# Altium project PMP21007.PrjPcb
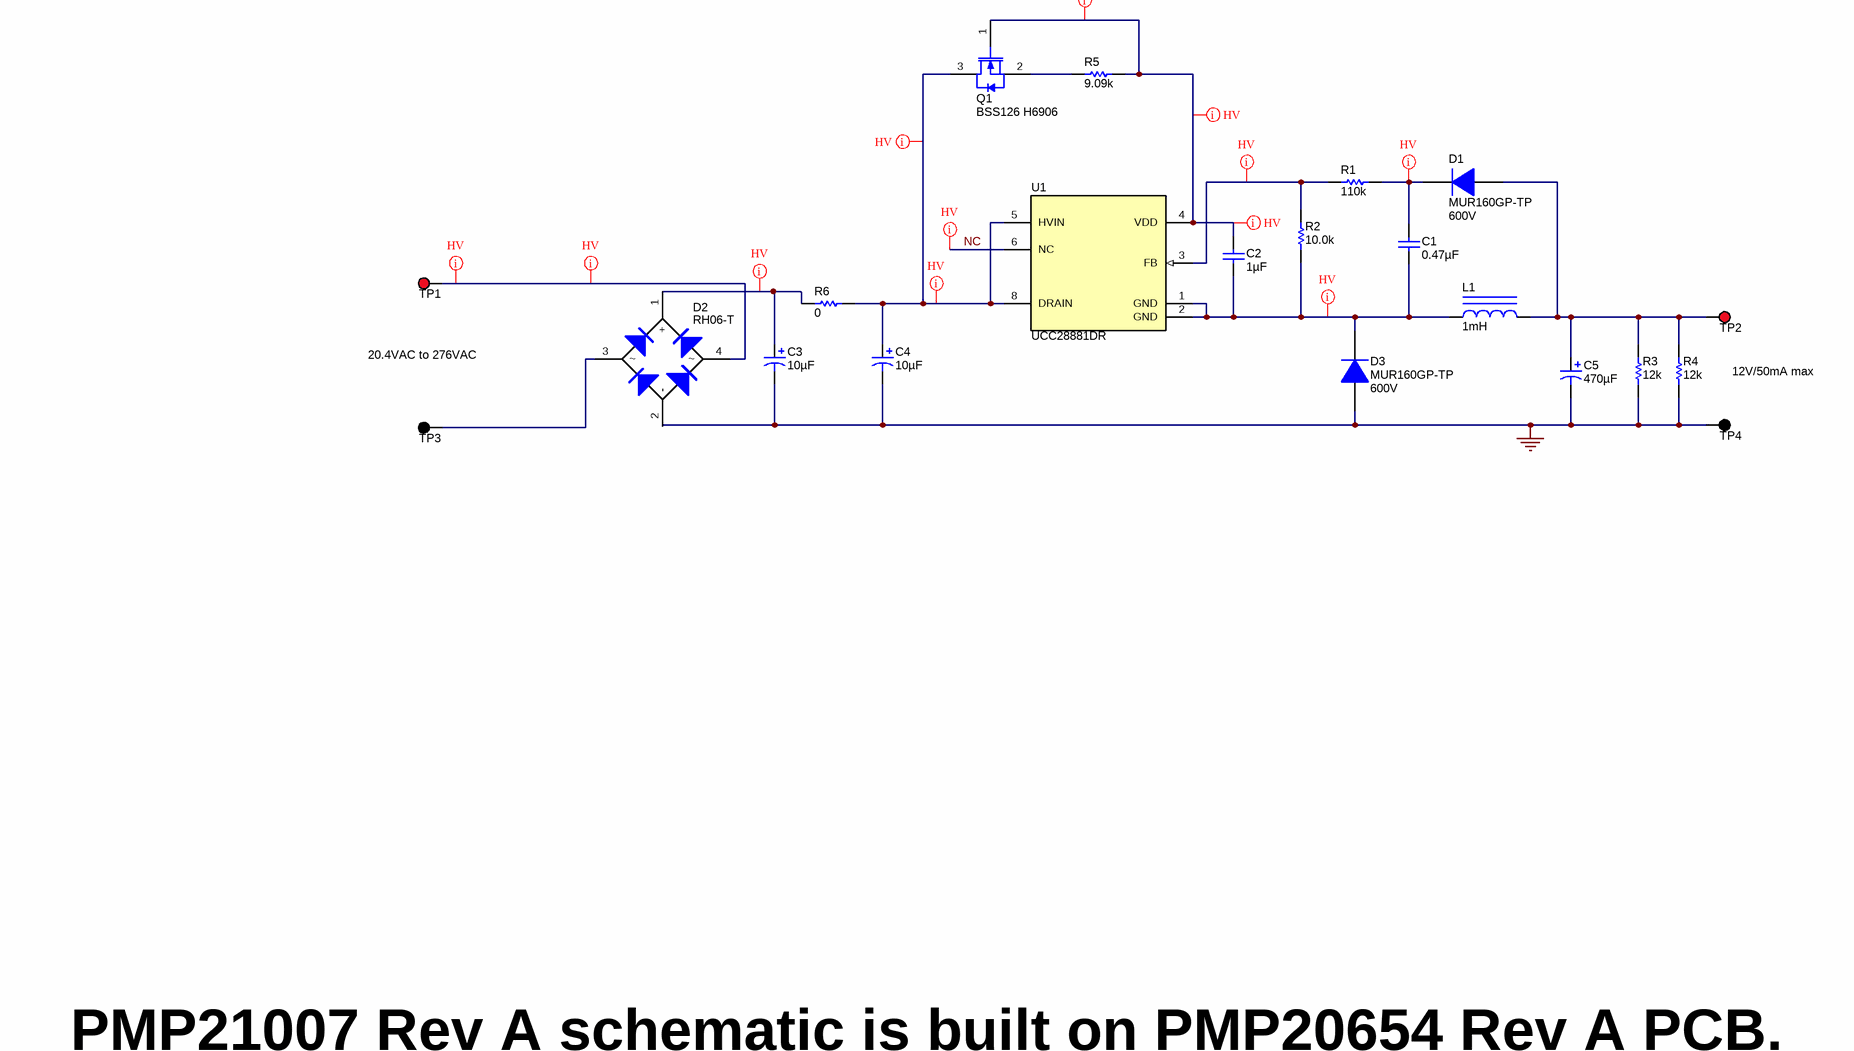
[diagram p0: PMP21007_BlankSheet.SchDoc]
CopyrightYear: 2017; PCB_Rev: A; PRJ_Customer: Public Release; PRJ_Engineer: Sonal Singh; PRJ_Number: PMP21007; PRJ_Title: UCC28881 High side Buck; SCH_Rev: A; TechSupport: http://www.ti.com/support; TID: N/A
1 sheet, 21 parts. Net scope: global (net labels, ports and power ports of the same name join across sheets).
Board file: PMP21007_PCB.PcbDoc

## Sheet PMP21007_BlankSheet.SchDoc
size 431 x 279 mm; Date: Not shown in title block; ApprovedBy: Not shown in title block; CheckedBy: Not shown in title block; Author: Not shown in title block; CompanyName: Not shown in title block; Engineer: Not shown in title block; Organization: Not shown in title block; Address1: Not shown in title block; Address2: Not shown in title block; Address3: Not shown in title block; Address4: Not shown in title block; DocumentNumber: 1; Revision: Use project parameter SCH_Rev; SheetNumber: 1; SheetTotal: 1; PageSetup: Record=PageOptions¦CenterHorizontal=True¦CenterVertical=True¦PrintScale=1.00¦XCorrection=1.00¦YCorrection=1.00¦PrintKind=0¦BorderSize=5000000¦LeftOffset=0¦BottomOffset=0¦Orientation=2¦PaperLength=1000¦PaperWidth=1000¦Scale=100¦PaperSource=15¦PrintQuality=600¦MediaType=1¦DitherType=10¦PaperKind=Letter¦PrintScaleMode=1

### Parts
C1  ValueDisplayed: 0.47µF  [0805_HV]  (hidden comment: 0805YC474JAT2A)
C2  ValueDisplayed: 1µF  [0805_HV]  (hidden comment: 0805YD105KAT2A)
C3  ValueDisplayed: 10µF  [CAPPR750W80D1600H1250]  (hidden comment: URU2G100MHD)
C4  ValueDisplayed: 10µF  [CAPPR750W80D1600H1250]  (hidden comment: URU2G100MHD)
C5  ValueDisplayed: 470µF  [KZN_1000x2000]  (hidden comment: EKZN350ELL471MJ20S)
D1  MUR160GP-TP  value 600V  [DO-41]
D2  RH06-T  [MiniDIP]
D3  MUR160GP-TP  value 600V  [DO-41]
L1  ValueDisplayed: 1mH  [WE-TI_9580]  (hidden comment: 744732102)
Q1  BSS126 H6906  [SOT-23]
R1  ValueDisplayed: 110k  [0603]  (hidden comment: RC0603FR-07110KL)
R2  value 10.0k  [0603]  (hidden comment: CRCW060310K0FKEA)
R3  value 12k  [1206]  (hidden comment: CRCW120612K0JNEA)
R4  value 12k  [1206]  (hidden comment: CRCW120612K0JNEA)
R5  ValueDisplayed: 9.09k  [0603]  (hidden comment: CRCW06039K09FKEA)
R6  ValueDisplayed: 0  [0603]  (hidden comment: CRCW06030000Z0EA)
TP1  5000  [Keystone5000]  (value not drawn)
TP2  5000  [Keystone5000]  (value not drawn)
TP3  5001  [Keystone5001]  (value not drawn)
TP4  5001  [Keystone5001]  (value not drawn)
U1  UCC28881DR  [D0007A_N]

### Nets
GND: C3.2(-) C4.2(-) C5.2(-) D2.2(-) D3.2(A) R3.1 R4.1 TP4.1
NC: U1.6(NC)
NetC1_1: C1.1 D1.1(K) R1.2
NetC1_2: C1.2 C2.2 D3.1(K) L1.1 R2.1 U1.1(GND) U1.2(GND)
NetC2_1: C2.1 Q1.1(G) R5.2 U1.4(VDD)
NetC3_1: C3.1(+) D2.1(+) R6.1
NetC4_1: C4.1(+) Q1.3(D) R6.2 U1.5(HVIN) U1.8(DRAIN)
NetC5_1: C5.1(+) D1.2(A) L1.2 R3.2 R4.2 TP2.1
NetD2_3: D2.3 TP3.1
NetD2_4: D2.4 TP1.1
NetQ1_2: Q1.2(S) R5.1
NetR1_1: R1.1 R2.2 U1.3(FB)

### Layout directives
net class HV: NC, NetC1_1, NetC1_2, NetC2_1, NetC3_1, NetC4_1, NetD2_4, NetR1_1

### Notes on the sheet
- 20.4VAC to 276VAC
- 12V/50mA max
- PMP21007 Rev A schematic is built on PMP20654 Rev A PCB.

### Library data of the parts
C1 = 0805YC474JAT2A: CAP, CERM, 0.47 µF, 16 V,+/- 5%, X7R, 0805; Manufacturer: AVX; Polarized: N; CompType: Capacitor; Value: 0.47uF; U/M: EA; Cap_F: 0.00000047; Tolerance_%: 5; ESR_ohm: 0.011; Value1: 0.011 ohm; VDC_V: 16; Value2: 16V; TaMin_C: -55; TaMax_C: 125; Cap_Case: 0805; SizeArea_mm2: 2.5; SizeAreaWB_mm2: 6.75; SizeX_mm: 2; SizeY_mm: 1.25; SizeZ_mm: 1.45; AEC Category: Q200; Green_Lifecycle: Active; Green_REACh: Passed
C2 = 0805YD105KAT2A: CAP, CERM, 1 µF, 16 V,+/- 10%, X5R, 0805; Manufacturer: AVX; Polarized: N; CompType: Capacitor; Value: 1uF; U/M: EA; Cap_F: 0.000001; Tolerance_%: 10; ESR_ohm: 0.012; Value1: 0.012 ohm; VDC_V: 16; Value2: 16V; TaMin_C: -55; TaMax_C: 85; Cap_Case: 0805; SizeArea_mm2: 2.5; SizeAreaWB_mm2: 6.75; SizeX_mm: 2; SizeY_mm: 1.25; SizeZ_mm: 1.45; AEC Category: Q200; Green_Lifecycle: Active; Green_REACh: Passed
C3 C4 = URU2G100MHD: CAP, AL, 10 µF, 400 V, +/- 20%, TH; Manufacturer: Nichicon; Polarized: Y; CompType: Capacitor; Value: 10uF; U/M: EA; Cap_F: 0.00001; Tolerance_%: 20; Value1: Unknown; VDC_V: 400; Value2: 400V; IRMS_A: 0.11; TaMin_C: -40; TaMax_C: 85; Cap_Case: RCAP, 16x12.5mm; SizeAreaWB_mm2: 324; SizeArea_mm2: 256; SizeX_mm: 16; SizeZ_mm: 14; AEC Category: Q200
C5 = EKZN350ELL471MJ20S: CAP, AL, 470 µF, 35 V, +/- 20%, 0.028 ohm, TH; Manufacturer: Chemi-Con; Polarized: Y; CompType: Capacitor; Value: 470uF; U/M: EA; Cap_F: 0.00047; Tolerance_%: 20; VDC_V: 35; Value2: 35V; ESR_ohm: 0.028; IRMS_A: 2.5; TaMin_C: -40; TaMax_C: 105; Cap_Case: 10x20mm; SizeAreaWB_mm2: 144; SizeArea_mm2: 100; SizeX_mm: 10; SizeZ_mm: 21.5; AEC Category: Q200
D1 D3 = 1N4007: Diode Standard 600V 1A Through Hole DO-41; Manufacturer: Micro Commercial Co; U/M: EA; Vf_V: 1.1; Value2: 1.1V; Io_A: 1; Vr_V: 600; TJmax_C: 175; RJC_CperW: 50; Type: P-N
D2 = RH06-T: Diode, Switching-Bridge, 600 V, 0.5 A, MiniDIP; Manufacturer: Diodes Inc.; U/M: EA; Vf_V: 1.15; Value: 600V; Value1: 0.5A; Value2: 1.15V; Io_A: 0.5; Vr_V: 600; TJmax_C: 150; SizeAreaWB_mm2: 62.1; SizeArea_mm2: 34.3; SizeX_mm: 7; SizeY_mm: 4.9; SizeZ_mm: 3; AEC Category: Q101; AEC Qualified: N; Green_Lifecycle: Active; Green_REACh: Passed
L1 = 744732102: Inductor, Wirewound, Ferrite, 1 mH, 0.33 A, 3.4 ohm, TH; Manufacturer: Wurth Elektronik; Value: 1mH; Ind_H: 1.0E-3; Imax_A: 0.33; Irms: 0.33A @ 40C rise; Isat: 0.6A @ 10% inductance drop; DCR_ohm: 3.4; Value1: 3.4 ohm; Value2: 0.33A; SizeAreaWB_mm2: 132.25; SizeArea_mm2: 90.25; SizeX_mm: 9.5; SizeZ_mm: 8; AEC Category: Q200; AEC Qualified: N
Q1 = BSS126 H6906: MOSFET, N-CH, 600 V, 0.021 A, AEC-Q101, SOT-23; Manufacturer: Infineon Technologies; Alternate Manufacturer: None; SymbolCreator: a0412235; U/M: EA; ChType: N; Value: 600V; VdsMax_V: 600; Value1: ? ohm; Value2: 1.4 nC; QgTyp_nC: 1.4; Vgs_V: 20; IdsMax_A: 0.021; SizeAreaWB_mm2: 14; SizeArea_mm2: 7.5; SizeX_mm: 2.5; SizeY_mm: 3; SizeZ_mm: 1.1; AEC Category: Q101; AEC Qualified: Y; Green_Lifecycle: Not Set; Green_REACh: Incomplete
R1 = RC0603FR-07110KL: RES, 110 k, 1%, 0.1 W, 0603; Manufacturer: Yageo America; CompType: Resistor; Value: 110k; Res_ohm: 110000; Tolerance_%: 1; Power_W: 0.1; Value2: 0.1W; VDC_V: 150; TempCo: 200 ppm/C; SizeArea_mm2: 1.28; SizeX_mm: 1.6; SizeY_mm: 0.8; EIA_Code: E96; U/M: EA; AEC Category: Q200
R2 = CRCW060310K0FKEA: RES, 10.0k ohm, 1%, 0.1W, 0603; Manufacturer: Vishay-Dale; CompType: Resistor; Res_ohm: 10000; Value_Code: 10k0; Tolerance_%: 1; Power_W: 0.1; VDC_V: 75; TempCo: 100 ppm/C; EIA_Code: E96; U/M: EA
R3 R4 = CRCW120612K0JNEA: RES, 12k ohm, 5%, 0.25W, 1206; Manufacturer: Vishay-Dale; CompType: Resistor; Res_ohm: 12000; Value_Code: 12k0; Tolerance_%: 5; Power_W: 0.25; VDC_V: 200; TempCo: 200 ppm/C; EIA_Code: E24; U/M: EA
R5 = CRCW06039K09FKEA: RES, 9.09 k, 1%, 0.1 W, 0603; Manufacturer: Vishay-Dale; CompType: Resistor; Value: 9.09k; Res_ohm: 9090; Value_Code: 9k09; Tolerance_%: 1; Power_W: 0.1; Value2: 0.1W; VDC_V: 75; TempCo: 100 ppm/C; SizeArea_mm2: 1.28; SizeX_mm: 1.6; SizeY_mm: 0.8; EIA_Code: E96; U/M: EA; AEC Category: Q200; Green_Lifecycle: Active; Green_REACh: Passed
R6 = CRCW06030000Z0EA: RES, 0, 5%, 0.1 W, 0603; Manufacturer: Vishay-Dale; CompType: Resistor; Value: 0; Value_Code: 0000; Tolerance_%: 5; Power_W: 0.1; Value2: 0.1W; VDC_V: 75; TempCo: 200 ppm/C; SizeArea_mm2: 1.28; SizeX_mm: 1.6; SizeY_mm: 0.8; SizeZ_mm: 1; EIA_Code: E24; U/M: EA; AEC Category: Q200; Green_Lifecycle: Active; Green_REACh: Passed
TP1 TP2 = 5000: Test Point, Miniature, Red, TH; Manufacturer: Keystone; CompType: Test Point Loop; ContactFinish: Silver
TP3 TP4 = 5001: Test Point, Miniature, Black, TH; Manufacturer: Keystone; CompType: Test Point Loop; ContactFinish: Silver
U1 = UCC28881DR: 700-V Lowest Quiescent Current Off-Line Switcher, D0007A (SOIC-7); Manufacturer: Texas Instruments; SymbolCreator: a0411947; SizeArea_mm2: 29.4; SizeAreaWB_mm2: 55.2; SizeX_mm: 6; SizeY_mm: 4.9; SizeZ_mm: 1.75; CompType: IC; U/M: EA

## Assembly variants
001: all parts fitted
